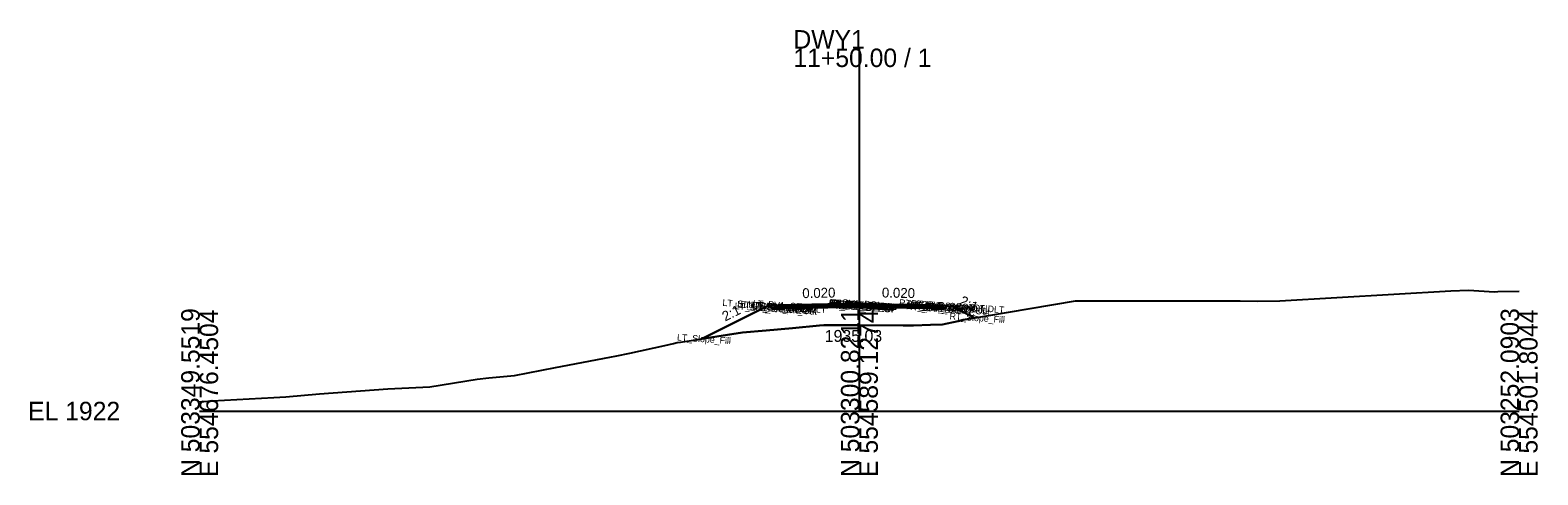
# Model space of a CAD drawing. Extents: x -26 to 203, y -10 to 1558.
# Drawn here: x -25.7 to 202.8, y 1490.3 to 1557.8 of the extents above; entities that cross this region are included whole.
import ezdxf

# ---------------------------------------------------------------- set-up
doc = ezdxf.new("R2010")
doc.units = 0
for name, color, linetype in [('Default', 7, 'Continuous'), ('Exist Cross Section Cell', 7, 'Continuous'), ('Exist XS Center Line Elevation Label', 7, 'Continuous'), ('Exist XS Ground Line', 7, 'Continuous'), ('Prop CMT Pvmt Course 1', 7, 'Continuous'), ('Prop CMT Pvmt Course 2', 7, 'Continuous'), ('Prop CMT Pvmt Surface', 7, 'Continuous'), ('Prop CMT Shld Paved Course 1', 7, 'Continuous'), ('Prop CMT Shld Paved Course 2', 7, 'Continuous'), ('Prop CMT Slope Grass', 7, 'Continuous'), ('Prop CMT Subgrade Earthwork', 7, 'Continuous'), ('Prop XS Earthwork Shape', 7, 'Continuous'), ('Prop XS SE Text', 7, 'Continuous'), ('Prop XS Side Slope Text', 7, 'Continuous'), ('Typical Text Asphalt at Bridge Approach CELL', 7, 'Continuous')]:
    doc.layers.add(name, color=color, linetype=linetype)

msp = doc.modelspace()

# ---------------------------------------------------------------- linework, layer by layer
at = {"layer": 'Exist Cross Section Cell'}
for p, q in [((100, 1500), (100, 1555.01)), ((0, 1500), (100, 1500)), ((100, 1500), (200, 1500))]:
    msp.add_line(p, q, dxfattribs=at)
at = {"layer": 'Exist XS Ground Line'}
for p, q in [((163.74, 1516.74), (189.64, 1518.25)), ((189.64, 1518.25), (192.31, 1518.34)), ((192.31, 1518.34), (196.29, 1518.07)), ((196.29, 1518.07), (196.77, 1518.12)), ((196.77, 1518.12), (200, 1518.18)), ((115.72, 1513.86), (132.77, 1516.75)), ((132.77, 1516.75), (135.65, 1516.75)), ((135.65, 1516.75), (146.96, 1516.75)), ((146.96, 1516.75), (147.4, 1516.72)), ((147.4, 1516.72), (157.72, 1516.74)), ((157.72, 1516.74), (160.34, 1516.66)), ((160.34, 1516.66), (163.74, 1516.74)), ((89.85, 1512.59), (93.96, 1512.97)), ((93.96, 1512.97), (94.59, 1513.04)), ((94.59, 1513.04), (95.68, 1513.04)), ((95.68, 1513.04), (96.02, 1513.04)), ((96.02, 1513.04), (96.77, 1513.05)), ((96.77, 1513.05), (100, 1513.03)), ((100, 1513.03), (106.65, 1512.98)), ((106.65, 1512.98), (107.79, 1512.98)), ((107.79, 1512.98), (108.18, 1512.99)), ((108.18, 1512.99), (110.8, 1513.06)), ((110.8, 1513.06), (112.59, 1513.13)), ((112.59, 1513.13), (114.95, 1513.62)), ((114.95, 1513.62), (115.72, 1513.86)), ((72.91, 1510.46), (82.26, 1511.91)), ((82.26, 1511.91), (85.89, 1512.23)), ((85.89, 1512.23), (89.85, 1512.59)), ((62.15, 1508.16), (63.24, 1508.37)), ((63.24, 1508.37), (65.21, 1508.8)), ((65.21, 1508.8), (70.51, 1509.97)), ((70.51, 1509.97), (71.84, 1510.27)), ((71.84, 1510.27), (72.36, 1510.39)), ((72.36, 1510.39), (72.91, 1510.46)), ((47.7, 1505.41), (53.95, 1506.59)), ((53.95, 1506.59), (62.15, 1508.16)), ((34.91, 1503.66), (42.08, 1504.86)), ((42.08, 1504.86), (43.82, 1505.06)), ((43.82, 1505.06), (47.7, 1505.41)), ((0, 1501.4), (1.91, 1501.54)), ((1.91, 1501.54), (11.26, 1502.03)), ((11.26, 1502.03), (13.05, 1502.16)), ((13.05, 1502.16), (18.16, 1502.6)), ((18.16, 1502.6), (28.53, 1503.38)), ((28.53, 1503.38), (34.91, 1503.66))]:
    msp.add_line(p, q, dxfattribs=at)
at = {"layer": 'Prop CMT Pvmt Course 1'}
for points in [[(100, 1516.3), (88, 1516.06)], [(88, 1516.06), (88, 1515.81)], [(88, 1515.81), (100, 1516.05)], [(100, 1516.05), (100, 1516.3)], [(100, 1516.3), (112, 1516.06)], [(100, 1516.05), (100, 1516.3)], [(112, 1515.81), (100, 1516.05)], [(112, 1516.06), (112, 1515.81)]]:
    msp.add_lwpolyline(points, dxfattribs=at)
msp.add_lwpolyline([(100, 1516.05), (100, 1516.18), (100, 1516.18), (100, 1516.05)], close=True, dxfattribs=at)
msp.add_lwpolyline([(100, 1516.05), (100, 1516.18), (100, 1516.18), (100, 1516.05)], close=True, dxfattribs=at)
at = {"layer": 'Prop CMT Pvmt Course 2'}
for points in [[(100, 1516.05), (88, 1515.81)], [(88, 1515.81), (88, 1515.56)], [(88, 1515.56), (100, 1515.8)], [(100, 1515.8), (100, 1516.05)], [(100, 1515.8), (100, 1516.05)], [(100, 1516.05), (112, 1515.81)], [(112, 1515.56), (100, 1515.8)], [(112, 1515.81), (112, 1515.56)]]:
    msp.add_lwpolyline(points, dxfattribs=at)
at = {"layer": 'Prop CMT Pvmt Surface'}
for points in [[(100, 1516.3), (88, 1516.06)], [(100, 1516.3), (112, 1516.06)]]:
    msp.add_lwpolyline(points, dxfattribs=at)
at = {"layer": 'Prop CMT Shld Paved Course 1'}
for points in [[(88, 1516.06), (87.74, 1515.81)], [(87.74, 1515.81), (88, 1515.81)], [(88, 1515.81), (88, 1516.06)], [(112, 1516.06), (112.26, 1515.81)], [(112, 1515.81), (112, 1516.06)], [(112.26, 1515.81), (112, 1515.81)]]:
    msp.add_lwpolyline(points, dxfattribs=at)
at = {"layer": 'Prop CMT Shld Paved Course 2'}
for points in [[(88, 1515.81), (87.74, 1515.81), (87.24, 1515.8), (86.99, 1515.54)], [(86.99, 1515.54), (88, 1515.56)], [(88, 1515.56), (88, 1515.81)], [(112, 1515.81), (112.26, 1515.81), (112.76, 1515.8), (113.01, 1515.54)], [(112, 1515.56), (112, 1515.81)], [(113.01, 1515.54), (112, 1515.56)]]:
    msp.add_lwpolyline(points, dxfattribs=at)
at = {"layer": 'Prop CMT Slope Grass'}
for points in [[(88, 1516.06), (86, 1515.9), (76.11, 1510.96)], [(112, 1516.06), (114, 1515.9), (117.49, 1514.16)]]:
    msp.add_lwpolyline(points, dxfattribs=at)
at = {"layer": 'Prop CMT Subgrade Earthwork'}
for points in [[(88, 1515.56), (86.99, 1515.54), (86.58, 1515.95)], [(100, 1515.8), (88, 1515.56)], [(100, 1515.8), (112, 1515.56)], [(112, 1515.56), (113.01, 1515.54), (113.42, 1515.95)]]:
    msp.add_lwpolyline(points, dxfattribs=at)
at = {"layer": 'Prop XS Earthwork Shape'}
msp.add_lwpolyline([(113.42, 1515.95), (114, 1515.9), (117.49, 1514.16), (115.72, 1513.86), (114.95, 1513.62), (112.59, 1513.13), (110.8, 1513.06), (108.18, 1512.99), (107.79, 1512.98), (106.65, 1512.98), (100, 1513.03), (96.77, 1513.05), (96.02, 1513.04), (95.68, 1513.04), (94.59, 1513.04), (93.96, 1512.97), (89.85, 1512.59), (85.89, 1512.23), (82.26, 1511.91), (76.11, 1510.96), (86, 1515.9), (86.58, 1515.95), (86.99, 1515.54), (88, 1515.56), (100, 1515.8), (112, 1515.56), (113.01, 1515.54)], close=True, dxfattribs=at)

# ---------------------------------------------------------------- texts
at = {"layer": 'Default'}
msp.add_text('-', height=0.0001, dxfattribs=at).set_placement((0, 1500))
at = {"layer": 'Exist Cross Section Cell'}
for s, p in [('DWY1', (90, 1555.01)), ('11+50.00 / 1', (90, 1552.21)), ('EL 1922', (-26, 1498.6))]:
    msp.add_text(s, height=2.8, dxfattribs=at).set_placement(p)
for s, p in [('N 503349.5519', (0, 1490)), ('E 554676.4504', (2.8, 1490)), ('N 503300.8211', (100, 1490)), ('E 554589.1274', (102.8, 1490)), ('N 503252.0903', (200, 1490)), ('E 554501.8044', (202.8, 1490))]:
    msp.add_text(s, height=2.8, rotation=90, dxfattribs=at).set_placement(p)
at = {"layer": 'Exist XS Center Line Elevation Label'}
msp.add_text('1935.03', height=1.8, dxfattribs=at).set_placement((94.75, 1510.5))
at = {"layer": 'Prop XS SE Text'}
for rotation, p in [(1.1458, (91.36, 1517.13)), (358.8542, (103.4, 1517.24))]:
    msp.add_text('0.020', height=1.5, rotation=rotation, dxfattribs=at).set_placement(p)
at = {"layer": 'Prop XS Side Slope Text'}
for rotation, p in [(26.5651, (79.66, 1513.57)), (333.4349, (115.02, 1516.23))]:
    msp.add_text('2:1', height=1.5, rotation=rotation, dxfattribs=at).set_placement(p)
at = {"layer": 'Typical Text Asphalt at Bridge Approach CELL'}
for s, p in [('LT_Sub_Trench_Out_DLT', (79.22, 1515.96)), ('LT_Sub_Trench_Out', (81.08, 1515.46)), ('LT_GS_OS_CTL', (81.44, 1515.72)), ('LT_PS2_Shelf_Out', (81.88, 1515.67)), ('LT_PS2_OEOP', (83.51, 1515.6)), ('LT_PV2_OEOT', (83.72, 1515.61)), ('LT_Sub_OEOT', (83.74, 1515.36)), ('LT_PV1_OEOT', (83.84, 1515.85)), ('RT_PV2_OEEOP', (95.31, 1515.88)), ('RT_Sub_OEEOP', (95.33, 1515.63)), ('LT_PV2_OEEOP', (95.37, 1515.88)), ('LT_Sub_OEEOP', (95.39, 1515.62)), ('RT_PV1_OEEOP', (95.43, 1516)), ('LT_PV1_OEEOP', (95.49, 1515.99)), ('RT_PV2_IEEOP', (95.69, 1515.85)), ('LT_PV2_IEEOP', (95.75, 1515.85)), ('RT_PV1_IEEOP', (95.81, 1515.97)), ('LT_PV1_IEEOP', (95.87, 1515.97)), ('PV2_PGL', (97.32, 1515.74)), ('PV1_PGL', (97.44, 1515.98)), ('RT_Sub_Trench_Out_DLT', (105.99, 1515.97)), ('RT_Sub_Trench_Out', (107.04, 1515.46)), ('RT_PS2_Shelf_Out', (107.33, 1515.68)), ('RT_PV2_OEOT', (107.66, 1515.62)), ('RT_Sub_OEOT', (107.69, 1515.36)), ('RT_PV1_OEOT', (107.78, 1515.86)), ('RT_PS2_OEOP', (107.96, 1515.61)), ('RT_GS_OS_CTL', (109.38, 1515.73)), ('RT_Slope_Fill', (113.64, 1513.93)), ('LT_Slope_Fill', (72.33, 1510.72))]:
    msp.add_text(s, height=1, rotation=356, dxfattribs=at).set_placement(p)

doc.saveas('drawing.dxf')
